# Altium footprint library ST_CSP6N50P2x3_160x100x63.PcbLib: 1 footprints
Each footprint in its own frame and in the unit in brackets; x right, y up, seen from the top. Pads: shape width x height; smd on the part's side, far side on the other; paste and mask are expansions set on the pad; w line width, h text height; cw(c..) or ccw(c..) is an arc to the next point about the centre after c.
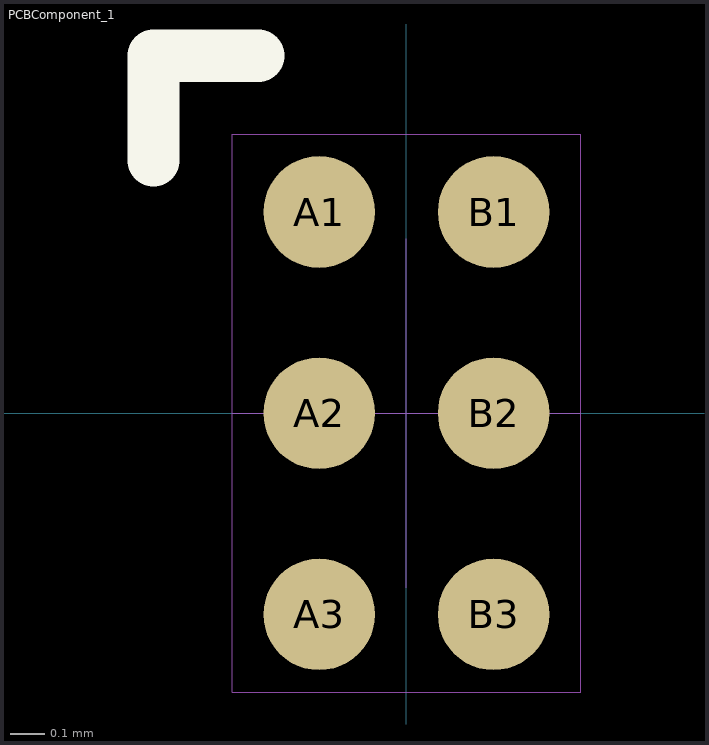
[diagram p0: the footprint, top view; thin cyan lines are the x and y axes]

## PCBComponent_1 [mm]
pads (6):
  round 0.32 smd paste-20 mask-0.05: A1(-0.25,0.577) A2(-0.25,0) A3(-0.25,-0.577) B1(0.25,0.577) B2(0.25,0) B3(0.25,-0.577)
Top Overlay:
  lines w0.15: -0.725,0.725 -0.725,1.025 -0.425,1.025
Top Paste:
  rectangle: -0.801,0.399 -0.793,0.414
  rectangle: -0.359,-0.113 -0.14,0.11
  rectangle: -0.359,-0.69 -0.14,-0.467
  rectangle: 0.141,0.464 0.36,0.687
  rectangle: 0.141,-0.113 0.36,0.11
  rectangle: 0.141,-0.69 0.36,-0.467
  rectangle: -0.359,0.464 -0.14,0.687
Mechanical 1:
  lines w0.001: -0.5,0 0.5,0 ; -0.5,0 0.5,0 ; -0.5,0 0.5,0 ; 0,-0.5 0,0.5 ; 0,-0.5 0,0.5 ; 0,-0.5 0,0.5
Mechanical 15:
  lines w0: -0.5,-0.8 0.5,-0.8 0.5,0.8 -0.5,0.8 -0.5,-0.8
3D body: height 0.68, standoff 0.18, extent -0.5,-0.8 0.5,0.8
